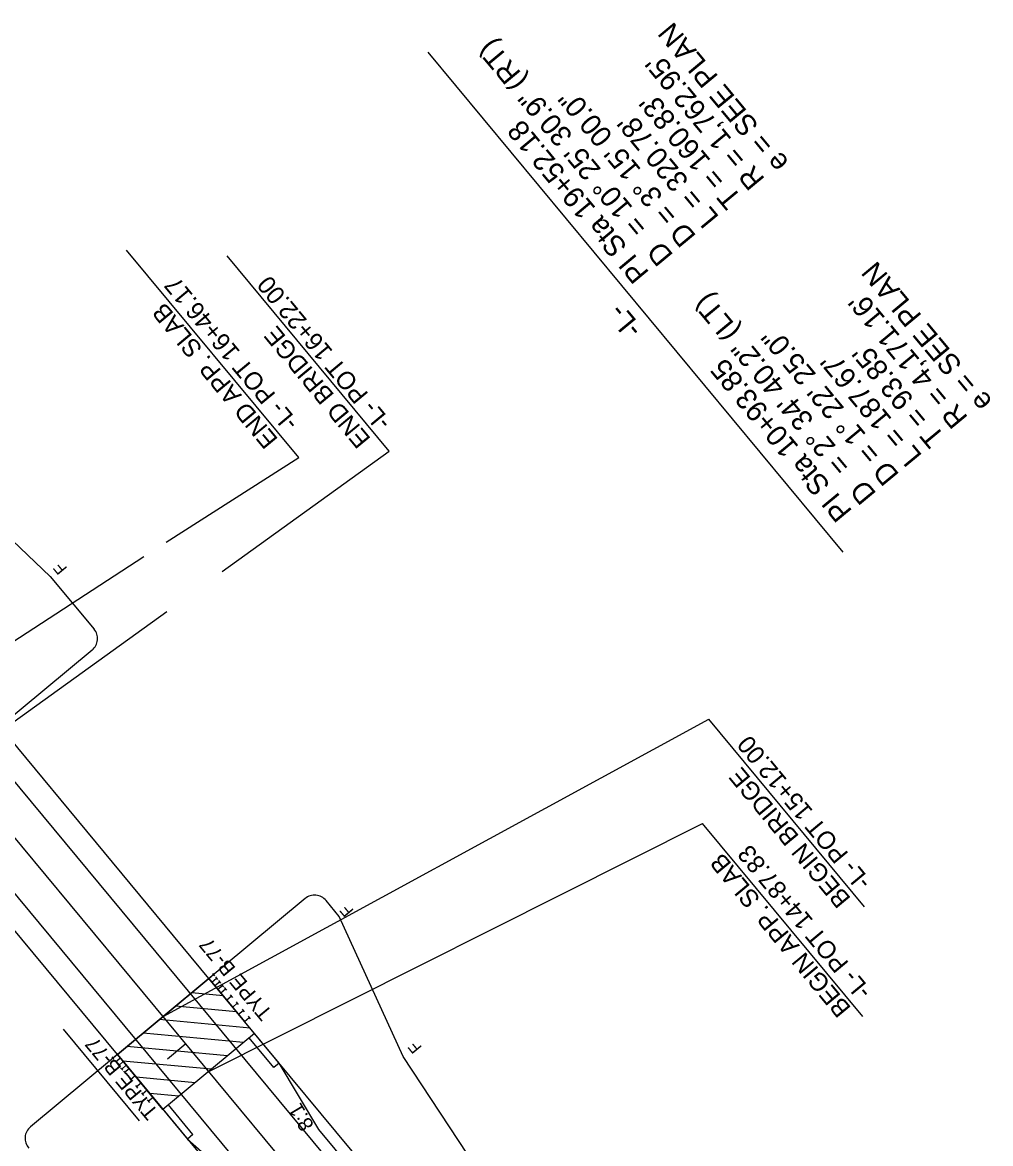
# Model space of a CAD drawing. Extents: x 2597570 to 2598622, y 852675 to 853890.
# Drawn here: x 2598022 to 2598347.5, y 853191.7 to 853568.5 of the extents above; entities that cross this region are included whole.
import ezdxf

# ---------------------------------------------------------------- set-up
doc = ezdxf.new("R2010")
doc.units = 0
for name, color, linetype in [('Exist Hydrographic Channel Edge', 7, 'Continuous'), ('Exist Hydrographic Top of Bank', 7, 'Continuous'), ('Prop Drainage Structure Drop Inlet Grate 2 Narrow Slots and Flat Grates 840 29 CELL', 7, 'Continuous'), ('Prop Drainage Structure Drop Inlet Grate 2 Narrow Slots and Flat Grates 840 29 TB CELL', 7, 'Continuous'), ('Prop Drainage Structure Pipe Alternate 15in Label', 7, 'Continuous'), ('Prop Drainage Structure Pipe RCP 15in Class IV', 7, 'Continuous'), ('Prop Drainage Structure Pipe RCP 15in Class IV Label', 7, 'Continuous'), ('Prop Drainage Structure Plot Symbol 20 Scale', 7, 'Continuous'), ('Prop Drainage Structure Plot Symbol 50 Scale', 7, 'Continuous'), ('Prop Earthen Structure Base Ditch Berm Detail Label', 7, 'Continuous'), ('Prop Earthen Structure V Ditch Lateral Detail CELL', 7, 'Continuous'), ('Prop Earthen Structure V Ditch Special Lateral Detail CELL', 7, 'Continuous'), ('Prop Erosion Rip Rap Pad at Outlet CELL', 7, 'Continuous'), ('Prop Erosion Rip Rap Pad at Outlet Label', 7, 'Continuous'), ('Prop Plan Preparation Crest', 7, 'Continuous'), ('Prop Plan Preparation Sketches Hydraulic Ditch', 7, 'Continuous'), ('Scratch_Level_3', 7, 'Continuous')]:
    doc.layers.add(name, color=color, linetype=linetype)

msp = doc.modelspace()

# ---------------------------------------------------------------- linework, layer by layer
at = {"layer": 'Exist Hydrographic Channel Edge'}
msp.add_line((2598276.51, 852984.93), (2597890.84, 853449.35), dxfattribs=at)
msp.add_line((2598276.51, 852984.93), (2597890.84, 853449.35), dxfattribs=at)
at = {"layer": 'Exist Hydrographic Top of Bank'}
msp.add_line((2598297.91, 853390.43), (2598158.38, 853558.45), dxfattribs=at)
at = {"layer": 'Prop Drainage Structure Drop Inlet Grate 2 Narrow Slots and Flat Grates 840 29 CELL'}
for p, q in [((2598084.72, 853247.19), (2598086.26, 853248.46)), ((2598085.9, 853248.9), (2598086.63, 853248.02)), ((2598084.72, 853247.19), (2598096.7, 853232.76)), ((2598085.72, 853245.98), (2598087.26, 853247.26)), ((2598086.72, 853244.78), (2598088.26, 853246.06)), ((2598086.89, 853247.7), (2598087.63, 853246.82)), ((2598087.72, 853243.58), (2598089.26, 853244.86)), ((2598087.89, 853246.5), (2598088.62, 853245.62)), ((2598088.89, 853245.3), (2598089.62, 853244.42)), ((2598089.89, 853244.1), (2598090.62, 853243.21)), ((2598088.72, 853242.38), (2598090.26, 853243.65)), ((2598090.71, 853239.97), (2598092.25, 853241.25)), ((2598091.89, 853241.69), (2598092.62, 853240.81)), ((2598092.71, 853237.57), (2598094.25, 853238.85)), ((2598093.88, 853239.29), (2598094.61, 853238.41)), ((2598095.88, 853236.88), (2598096.61, 853236)), ((2598094.71, 853235.16), (2598096.24, 853236.44)), ((2598096.7, 853232.76), (2598098.24, 853234.04)), ((2598097.87, 853234.48), (2598098.61, 853233.6)), ((2598053.95, 853221.63), (2598052.41, 853220.35)), ((2598053.95, 853221.63), (2598065.93, 853207.21)), ((2598052.05, 853220.79), (2598052.78, 853219.91)), ((2598053.04, 853219.59), (2598053.78, 853218.71)), ((2598054.95, 853220.43), (2598053.41, 853219.15)), ((2598054.04, 853218.39), (2598054.77, 853217.51)), ((2598055.95, 853219.23), (2598054.41, 853217.95)), ((2598056.95, 853218.02), (2598055.41, 853216.75)), ((2598055.04, 853217.19), (2598055.77, 853216.31)), ((2598056.04, 853215.99), (2598056.77, 853215.1)), ((2598057.94, 853216.82), (2598056.4, 853215.55)), ((2598059.94, 853214.42), (2598058.4, 853213.14)), ((2598058.04, 853213.58), (2598058.77, 853212.7)), ((2598060.03, 853211.18), (2598060.76, 853210.3)), ((2598061.94, 853212.01), (2598060.4, 853210.74)), ((2598062.03, 853208.77), (2598062.76, 853207.89)), ((2598063.93, 853209.61), (2598062.39, 853208.33)), ((2598064.02, 853206.37), (2598064.76, 853205.49)), ((2598065.93, 853207.21), (2598064.39, 853205.93))]:
    msp.add_line(p, q, dxfattribs=at)
at = {"layer": 'Prop Drainage Structure Drop Inlet Grate 2 Narrow Slots and Flat Grates 840 29 TB CELL'}
for p, q in [((2598084.72, 853247.19), (2598014.45, 853331.81)), ((2598053.95, 853221.63), (2597983.68, 853306.26)), ((2598084.72, 853247.19), (2598053.95, 853221.63))]:
    msp.add_line(p, q, dxfattribs=at)
at = {"layer": 'Prop Drainage Structure Pipe RCP 15in Class IV'}
for p, q in [((2598031.35, 853382.31), (2597994.87, 853417.01)), ((2598031.35, 853382.31), (2598046.11, 853364.62)), ((2598045.47, 853357.57), (2597953.3, 853281.03)), ((2598117.05, 853274.03), (2598024.72, 853197.36)), ((2598128.5, 853268.01), (2598124.11, 853273.36)), ((2598150.05, 853220.91), (2598128.5, 853268.01)), ((2598177.77, 853178.93), (2598150.05, 853220.91))]:
    msp.add_line(p, q, dxfattribs=at)
for centre, start, end in [((2598042.28, 853361.42), 309.7067, 39.8613), ((2598120.24, 853270.18), 39.4088, 129.7067), ((2598027.92, 853193.51), 129.7067, 221.8952)]:
    msp.add_arc(centre, 5, start, end, dxfattribs=at)
at = {"layer": 'Prop Drainage Structure Pipe RCP 15in Class IV Label'}
for p, q in [((2598114.95, 853422.25), (2598057.07, 853491.95)), ((2598145.37, 853424.42), (2598090.87, 853490.05)), ((2598070.33, 853393.84), (2598114.95, 853422.25)), ((2598089.19, 853383.97), (2598145.37, 853424.42)), ((2597983.7, 853337.54), (2598062.79, 853389.05)), ((2597999.06, 853319.03), (2598070.55, 853370.55)), ((2598069.34, 853234.41), (2598252.78, 853334.35)), ((2598305.14, 853271.31), (2598252.78, 853334.35)), ((2598084.67, 853215.94), (2598250.61, 853299.31)), ((2598304.54, 853234.38), (2598250.61, 853299.31))]:
    msp.add_line(p, q, dxfattribs=at)
at = {"layer": 'Prop Drainage Structure Plot Symbol 20 Scale'}
for p, q in [((2598285.74, 852992.6), (2597900.08, 853457.02)), ((2598267.28, 852977.26), (2597881.61, 853441.69))]:
    msp.add_line(p, q, dxfattribs=at)
at = {"layer": 'Prop Drainage Structure Plot Symbol 50 Scale'}
for p, q in [((2598106.53, 853217.26), (2598098.25, 853227.22)), ((2598108.32, 853218.75), (2598106.53, 853217.26)), ((2598121.7, 853196.4), (2598108.32, 853218.75)), ((2598079.35, 853194.7), (2598071.08, 853204.66)), ((2598288.82, 852995.15), (2598121.7, 853196.4)), ((2598079.35, 853194.7), (2598077.56, 853193.2)), ((2598077.56, 853193.2), (2598097.17, 853175.85))]:
    msp.add_line(p, q, dxfattribs=at)
at = {"layer": 'Prop Earthen Structure V Ditch Lateral Detail CELL'}
for p, q in [((2598089.53, 853241.39), (2598078.93, 853242.37)), ((2598094.04, 853235.95), (2598073.49, 853237.85)), ((2598098.55, 853230.51), (2598068.05, 853233.34)), ((2598096.4, 853225.69), (2598062.61, 853228.82)), ((2598090.96, 853221.17), (2598057.17, 853224.3)), ((2598085.52, 853216.65), (2598055.8, 853219.41)), ((2598080.08, 853212.14), (2598060.31, 853213.97)), ((2598074.64, 853207.62), (2598064.83, 853208.53))]:
    msp.add_line(p, q, dxfattribs=at)
at = {"layer": 'Prop Earthen Structure V Ditch Special Lateral Detail CELL'}
msp.add_line((2598035.68, 853230.19), (2598061.31, 853199.3), dxfattribs=at)
at = {"layer": 'Prop Erosion Rip Rap Pad at Outlet CELL'}
for p, q in [((2598096.7, 853232.76), (2598084.72, 853247.19)), ((2598244.24, 853055.07), (2598096.7, 853232.76)), ((2598065.93, 853207.21), (2598053.95, 853221.63)), ((2598065.93, 853207.21), (2598111.78, 853151.99))]:
    msp.add_line(p, q, dxfattribs=at)
at = {"layer": 'Prop Plan Preparation Crest'}
msp.add_line((2598076.97, 853225.21), (2598070.82, 853220.1), dxfattribs=at)
at = {"layer": 'Prop Plan Preparation Sketches Hydraulic Ditch'}
for p, q in [((2598108.33, 853218.76), (2598084.72, 853247.19)), ((2598053.95, 853221.63), (2598077.56, 853193.2))]:
    msp.add_line(p, q, dxfattribs=at)
at = {"layer": 'Scratch_Level_3'}
for p, q in [((2598053.95, 853221.63), (2598084.72, 853247.19)), ((2598100.06, 853228.72), (2598084.72, 853247.19)), ((2598100.06, 853228.72), (2598069.28, 853203.17)), ((2598069.28, 853203.17), (2598053.95, 853221.63))]:
    msp.add_line(p, q, dxfattribs=at)

# ---------------------------------------------------------------- texts
at = {"layer": 'Exist Hydrographic Top of Bank'}
for s, p in [('e = SEE PLAN', (2598279.99, 853521.65)), ('= 10%%d 25\' 30.9" (RT)', (2598232.65, 853500.01)), ("R = 1,762.95'", (2598271.86, 853515.87)), ('D = 3%%d 15\' 00.0"', (2598248.78, 853496.71)), ("T = 160.83'", (2598264.17, 853509.48)), ('PI Sta 19+52.18', (2598232.97, 853484.45)), ("L = 320.78'", (2598256.48, 853503.09)), ('D', (2598241.09, 853490.32)), ('e = SEE PLAN', (2598348.4, 853441.28)), ('= 2%%d 34\' 40.2" (LT)', (2598300.92, 853419.85)), ("R = 4,171.16'", (2598340.13, 853435.71)), ('-L-', (2598230.76, 853465.73)), ('D = 1%%d 22\' 25.0"', (2598317.05, 853416.54)), ("T = 93.85'", (2598332.43, 853429.32)), ('PI Sta 10+93.85', (2598301.23, 853404.28)), ("L = 187.67'", (2598324.74, 853422.93)), ('D', (2598309.35, 853410.15))]:
    msp.add_text(s, height=7, rotation=129.7067, dxfattribs=at).set_placement(p)
at = {"layer": 'Prop Drainage Structure Drop Inlet Grate 2 Narrow Slots and Flat Grates 840 29 CELL'}
for p in [(2598106.3, 853235.76), (2598067.96, 853202.36)]:
    msp.add_text('TYPE B-77', height=5, rotation=129.7067, dxfattribs=at).set_placement(p)
at = {"layer": 'Prop Drainage Structure Pipe Alternate 15in Label'}
for s, p in [('-L- POT 16+46.17', (2598115.12, 853434.16)), ('-L- POT 16+22.00', (2598146.28, 853434.31)), ('END APP. SLAB', (2598108.2, 853428.41)), ('END BRIDGE', (2598139.35, 853428.56)), ('-L- POT 15+12.00', (2598307.66, 853279.81)), ('BEGIN BRIDGE', (2598300.74, 853274.06)), ('-L- POT 14+87.83', (2598307.77, 853243.03)), ('BEGIN APP. SLAB', (2598300.84, 853237.28))]:
    msp.add_text(s, height=6, rotation=129.7066, dxfattribs=at).set_placement(p)
at = {"layer": 'Prop Earthen Structure Base Ditch Berm Detail Label'}
for p in [(2598037.3, 853385.02), (2598133.6, 853269.99), (2598156.54, 853224.04)]:
    msp.add_text('F', height=4, rotation=129.7067, dxfattribs=at).set_placement(p)
at = {"layer": 'Prop Erosion Rip Rap Pad at Outlet Label'}
msp.add_text('8:1', height=5, rotation=120.9067, dxfattribs=at).set_placement((2598120.21, 853197.81))

doc.saveas('drawing.dxf')
